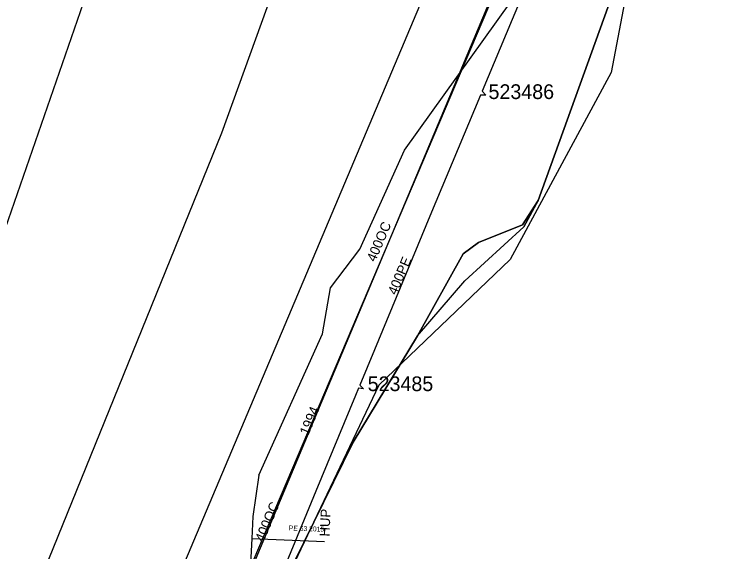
# Model space of a CAD drawing. Extents: x -746464 to -745690, y -1051581 to -1049993.
# Drawn here: x -746128 to -746055.3, y -1050483.9 to -1050429.1 of the extents above; entities that cross this region are included whole.
import ezdxf

# ---------------------------------------------------------------- set-up
doc = ezdxf.new("R2010")
doc.units = 0
for name, color, linetype in [('04_CETIN_sdelovaci_podzem', 7, 'Continuous'), ('10_CD_Telematika_metalika', 7, 'Continuous'), ('14_SZDC_SSZT_zabezp_orientacni', 7, 'Continuous'), ('45_Eltodo_popisy', 7, 'Continuous'), ('45_Eltodo_vedeni_NN_zemni', 7, 'Continuous'), ('48_Prazs_plynarenska_STL', 7, 'Continuous'), ('48_Prazs_plynarenska_STL_popisy', 7, 'Continuous'), ('51_PVaK_vodovod_overena poloha_rad', 7, 'Continuous'), ('51_PVaK_vodovod_popisy', 7, 'Continuous'), ('51_PVaK_vodovod_zruseno_overena poloha', 7, 'Continuous')]:
    doc.layers.add(name, color=color, linetype=linetype)

msp = doc.modelspace()

# ---------------------------------------------------------------- linework, layer by layer
at = {"layer": '04_CETIN_sdelovaci_podzem'}
for points in [[(-746074.47, -1050448.12), (-746066.03, -1050424.73), (-746065.78, -1050423.68)], [(-746066.03, -1050424.73), (-746074.47, -1050448.12)], [(-746074.47, -1050448.12), (-746076.06, -1050450.6), (-746080.56, -1050452.39), (-746082.14, -1050453.55), (-746086.77, -1050461.91), (-746093.36, -1050472.77), (-746104.43, -1050495.24)], [(-746086.77, -1050461.91), (-746081.96, -1050456.31), (-746075.94, -1050450.79), (-746074.47, -1050448.12)], [(-746086.77, -1050461.91), (-746082.14, -1050453.55), (-746080.56, -1050452.39), (-746076.06, -1050450.6), (-746074.47, -1050448.12)], [(-746074.47, -1050448.12), (-746075.94, -1050450.79)], [(-746104.43, -1050495.24), (-746093.36, -1050472.77), (-746086.77, -1050461.91)]]:
    msp.add_lwpolyline(points, dxfattribs=at)
at = {"layer": '10_CD_Telematika_metalika'}
msp.add_lwpolyline([(-746056.517, -1050380.079), (-746062.04, -1050408.989), (-746067.017, -1050435.04), (-746077.342, -1050454.12), (-746090.729, -1050466.957), (-746116.552, -1050521.207), (-746121.17, -1050569.408)], dxfattribs=at)
at = {"layer": '14_SZDC_SSZT_zabezp_orientacni'}
for points in [[(-745954.811, -1049995.554), (-745954.879, -1049999.999), (-745956.552, -1050024.162), (-745966.363, -1050070.726), (-745980.455, -1050112.942), (-745986.498, -1050129.102), (-746012.143, -1050119.513), (-746035.373, -1050181.639), (-746062.492, -1050277.378), (-746097.158, -1050370.696), (-746114.172, -1050408.516), (-746133.491, -1050464.214), (-746183.19, -1050596.884)], [(-745987.27, -1050128.814), (-746006.593, -1050179.795), (-746053.958, -1050301.166), (-746083.334, -1050376.44), (-746106.802, -1050441.246), (-746149.327, -1050545.88), (-746170.873, -1050602.004), (-746188.906, -1050653.16), (-746197.273, -1050674.612), (-746206.832, -1050708.097), (-746216.856, -1050759.718), (-746233.984, -1050757.648)]]:
    msp.add_lwpolyline(points, dxfattribs=at)
at = {"layer": '45_Eltodo_vedeni_NN_zemni'}
for points in [[(-746067.307, -1050407.418), (-746067.792, -1050407.369), (-746071.333, -1050415.924), (-746077.114, -1050429.664), (-746080.173, -1050436.945), (-746079.801, -1050437.362)], [(-746079.801, -1050437.362), (-746080.35, -1050437.367), (-746085.531, -1050449.696), (-746091.167, -1050463.33), (-746092.674, -1050466.951), (-746092.309, -1050467.321)], [(-746092.309, -1050467.321), (-746092.799, -1050467.253), (-746093.111, -1050468.002), (-746097.169, -1050477.752), (-746101.876, -1050489.147), (-746105.235, -1050497.067), (-746104.89, -1050497.41)]]:
    msp.add_lwpolyline(points, dxfattribs=at)
at = {"layer": '48_Prazs_plynarenska_STL'}
for points in [[(-746102.98, -1050476.12), (-746096.47, -1050461.7), (-746095.66, -1050457.03), (-746092.66, -1050453.08), (-746088.13, -1050442.96), (-746077.27, -1050427.84), (-746068.1, -1050414.24), (-746059.01, -1050400.57), (-746047.47, -1050381.79), (-746042.02, -1050368.4), (-746036.78, -1050355.46), (-746031.28, -1050341.86), (-746029.19, -1050336.38), (-746028.39, -1050332.74), (-746025.02, -1050315.94), (-746024.65, -1050314.09), (-746019.25, -1050298.02), (-746013.84, -1050282.13), (-746012.85, -1050280.13), (-746009.77, -1050272.08)], [(-746102.98, -1050476.12), (-746103.61, -1050480.34), (-746103.71, -1050482.6), (-746103.89, -1050486.51), (-746104.5, -1050489.79), (-746106.93, -1050495.83), (-746111.45, -1050506.32), (-746111.8, -1050507.12), (-746111.99, -1050507.57), (-746117.4, -1050520.13), (-746121.46, -1050530.02), (-746122.63, -1050532.92), (-746122.93, -1050533.42), (-746126.69, -1050542.33), (-746127.97, -1050544.91), (-746128.42, -1050547.13), (-746129.33, -1050554.38), (-746129.42, -1050555.21), (-746130.07, -1050559.3), (-746131.67, -1050568.69), (-746122.39, -1050575), (-746118.4, -1050577.73)], [(-746103.71, -1050482.6), (-746096.27, -1050482.9)]]:
    msp.add_lwpolyline(points, dxfattribs=at)
at = {"layer": '51_PVaK_vodovod_overena poloha_rad'}
msp.add_lwpolyline([(-746001.68, -1050242.13), (-746001.93, -1050242.8), (-746034.02, -1050320), (-746035.63, -1050323.96), (-746068.85, -1050403.49), (-746071.26, -1050408.86), (-746103.5, -1050484.68), (-746103.98, -1050485.78)], dxfattribs=at)
at = {"layer": '51_PVaK_vodovod_zruseno_overena poloha'}
msp.add_line((-746001.44, -1050242.09), (-746104.41, -1050487.26), dxfattribs=at)
msp.add_lwpolyline([(-745914.36, -1049995.554), (-745918.59, -1050000.44), (-745949.82, -1050104.56), (-746117.965, -1050502.507)], dxfattribs=at)

# ---------------------------------------------------------------- texts
at = {"layer": '45_Eltodo_popisy'}
for s, p in [('523486', (-746079.537, -1050437.76)), ('523485', (-746091.873, -1050467.551))]:
    msp.add_text(s, height=1.5, dxfattribs=at).set_placement(p)
at = {"layer": '48_Prazs_plynarenska_STL_popisy'}
for s, height, rotation, p in [('HUP', 1, 87.69, (-746095.77, -1050482.4)), ('PE 63 2015', 0.5, 357.69094, (-746099.931, -1050481.752))]:
    msp.add_text(s, height=height, rotation=rotation, dxfattribs=at).set_placement(p)
at = {"layer": '51_PVaK_vodovod_popisy'}
for s, rotation, p in [('400OC', 66.96441, (-746091.097, -1050454.44)), ('400PE', 66.96359, (-746088.944, -1050457.824)), ('1994', 67.21813, (-746097.937, -1050472.133)), ('400OC', 67.21811, (-746102.495, -1050483.02))]:
    msp.add_text(s, height=1, rotation=rotation, dxfattribs=at).set_placement(p)

doc.saveas('drawing.dxf')
